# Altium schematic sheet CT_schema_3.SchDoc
size 578 x 363 mm
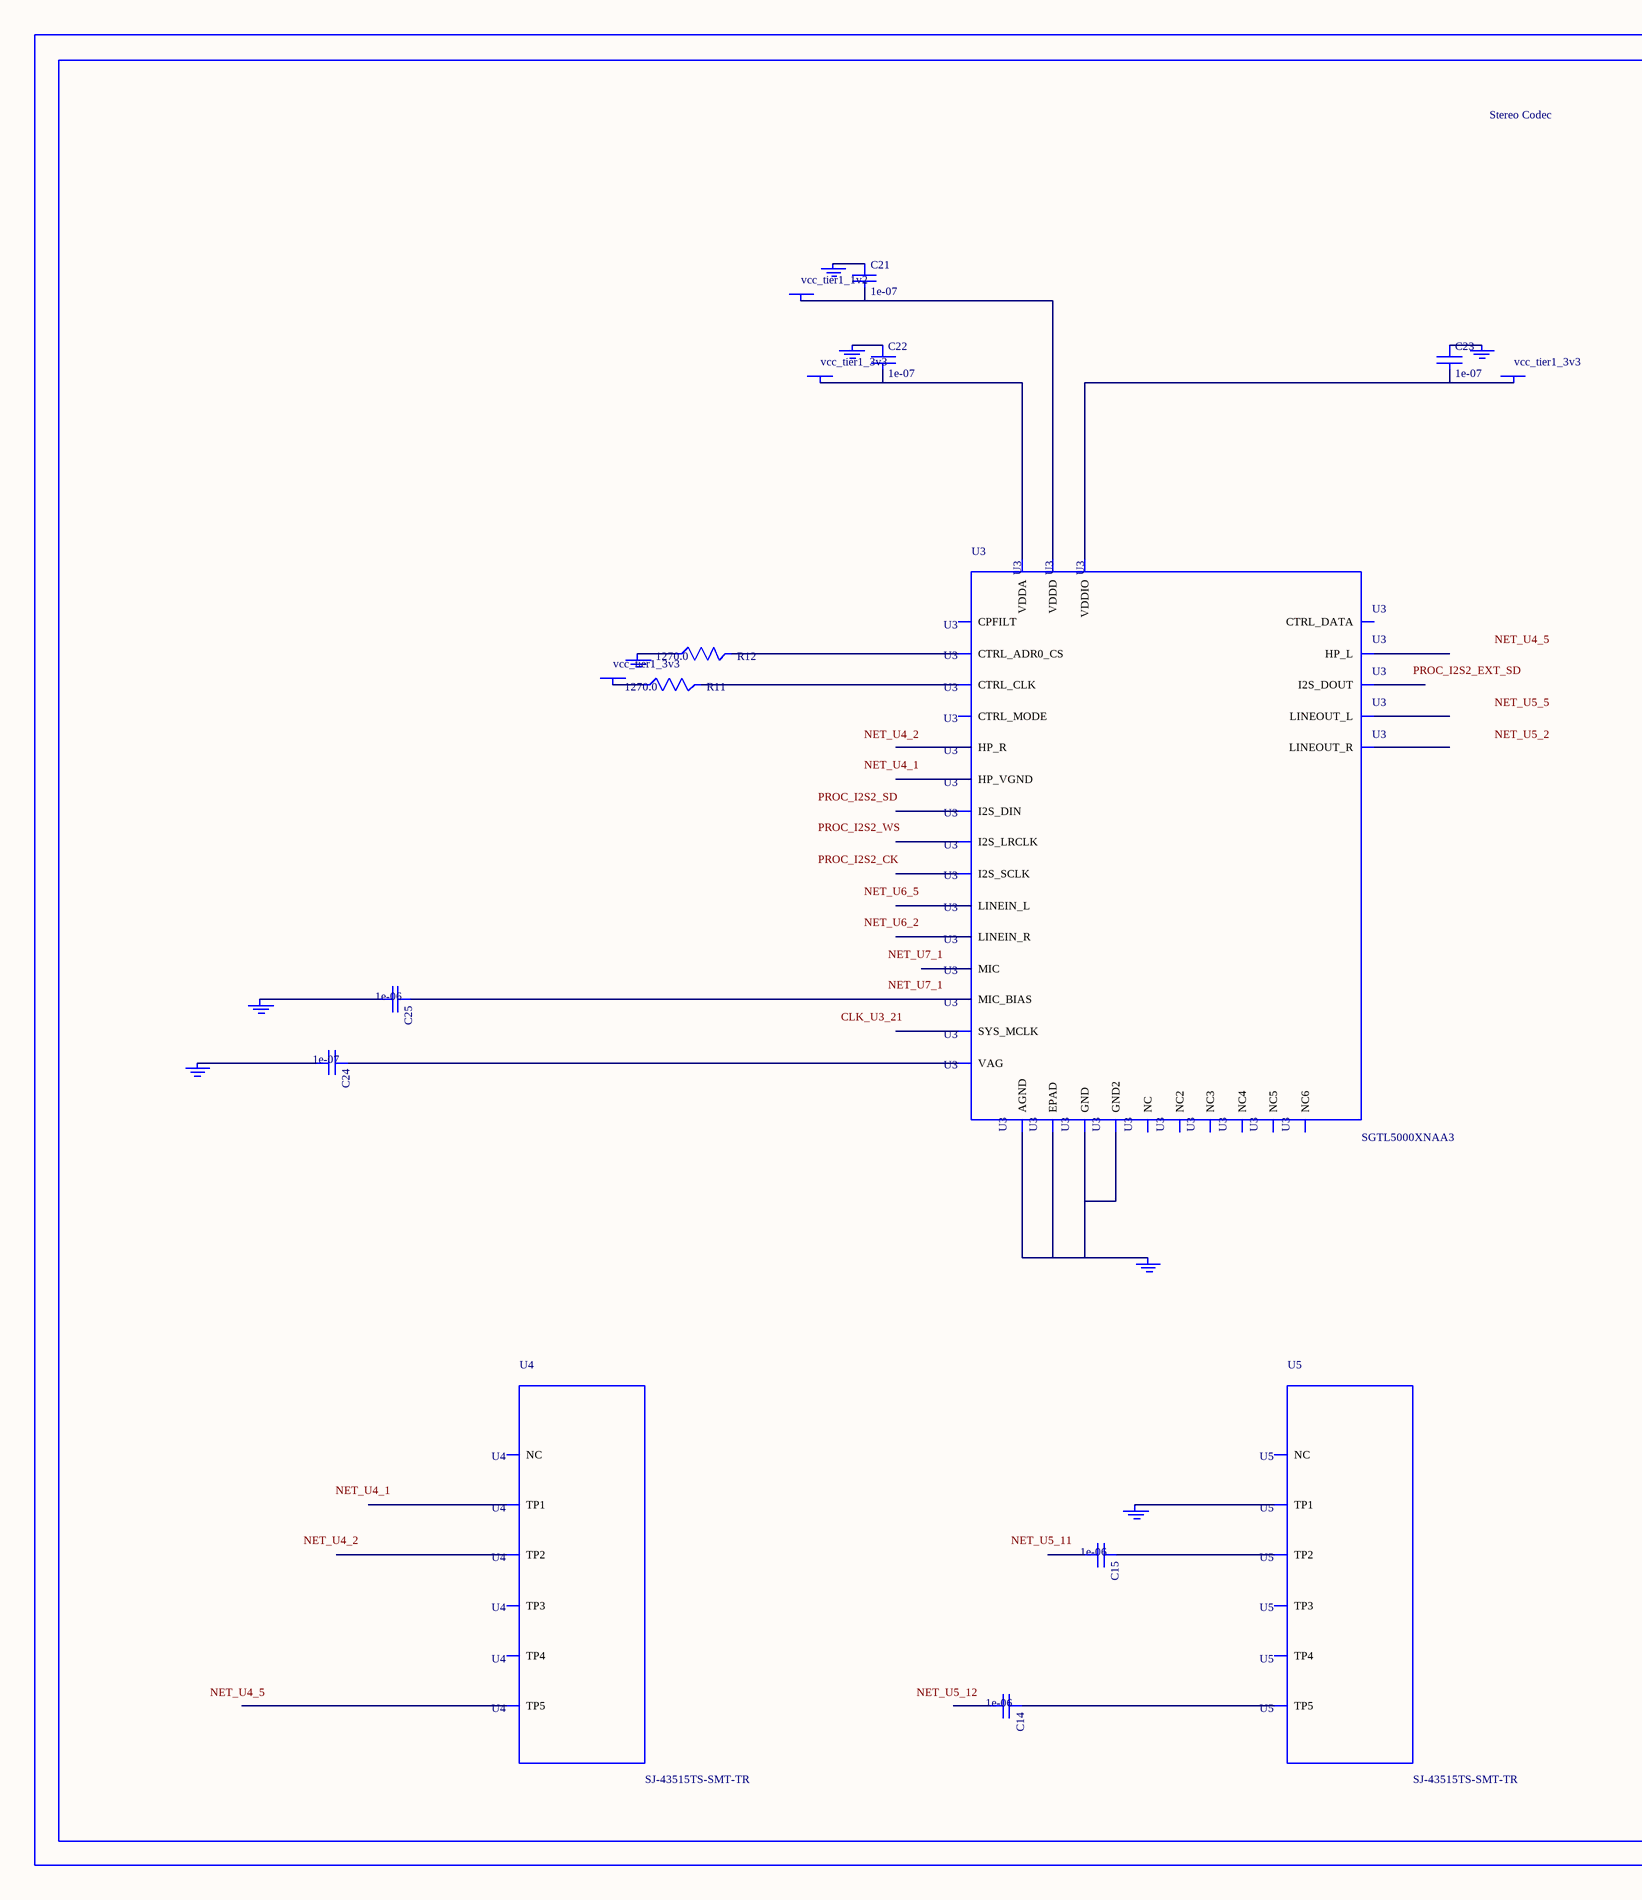
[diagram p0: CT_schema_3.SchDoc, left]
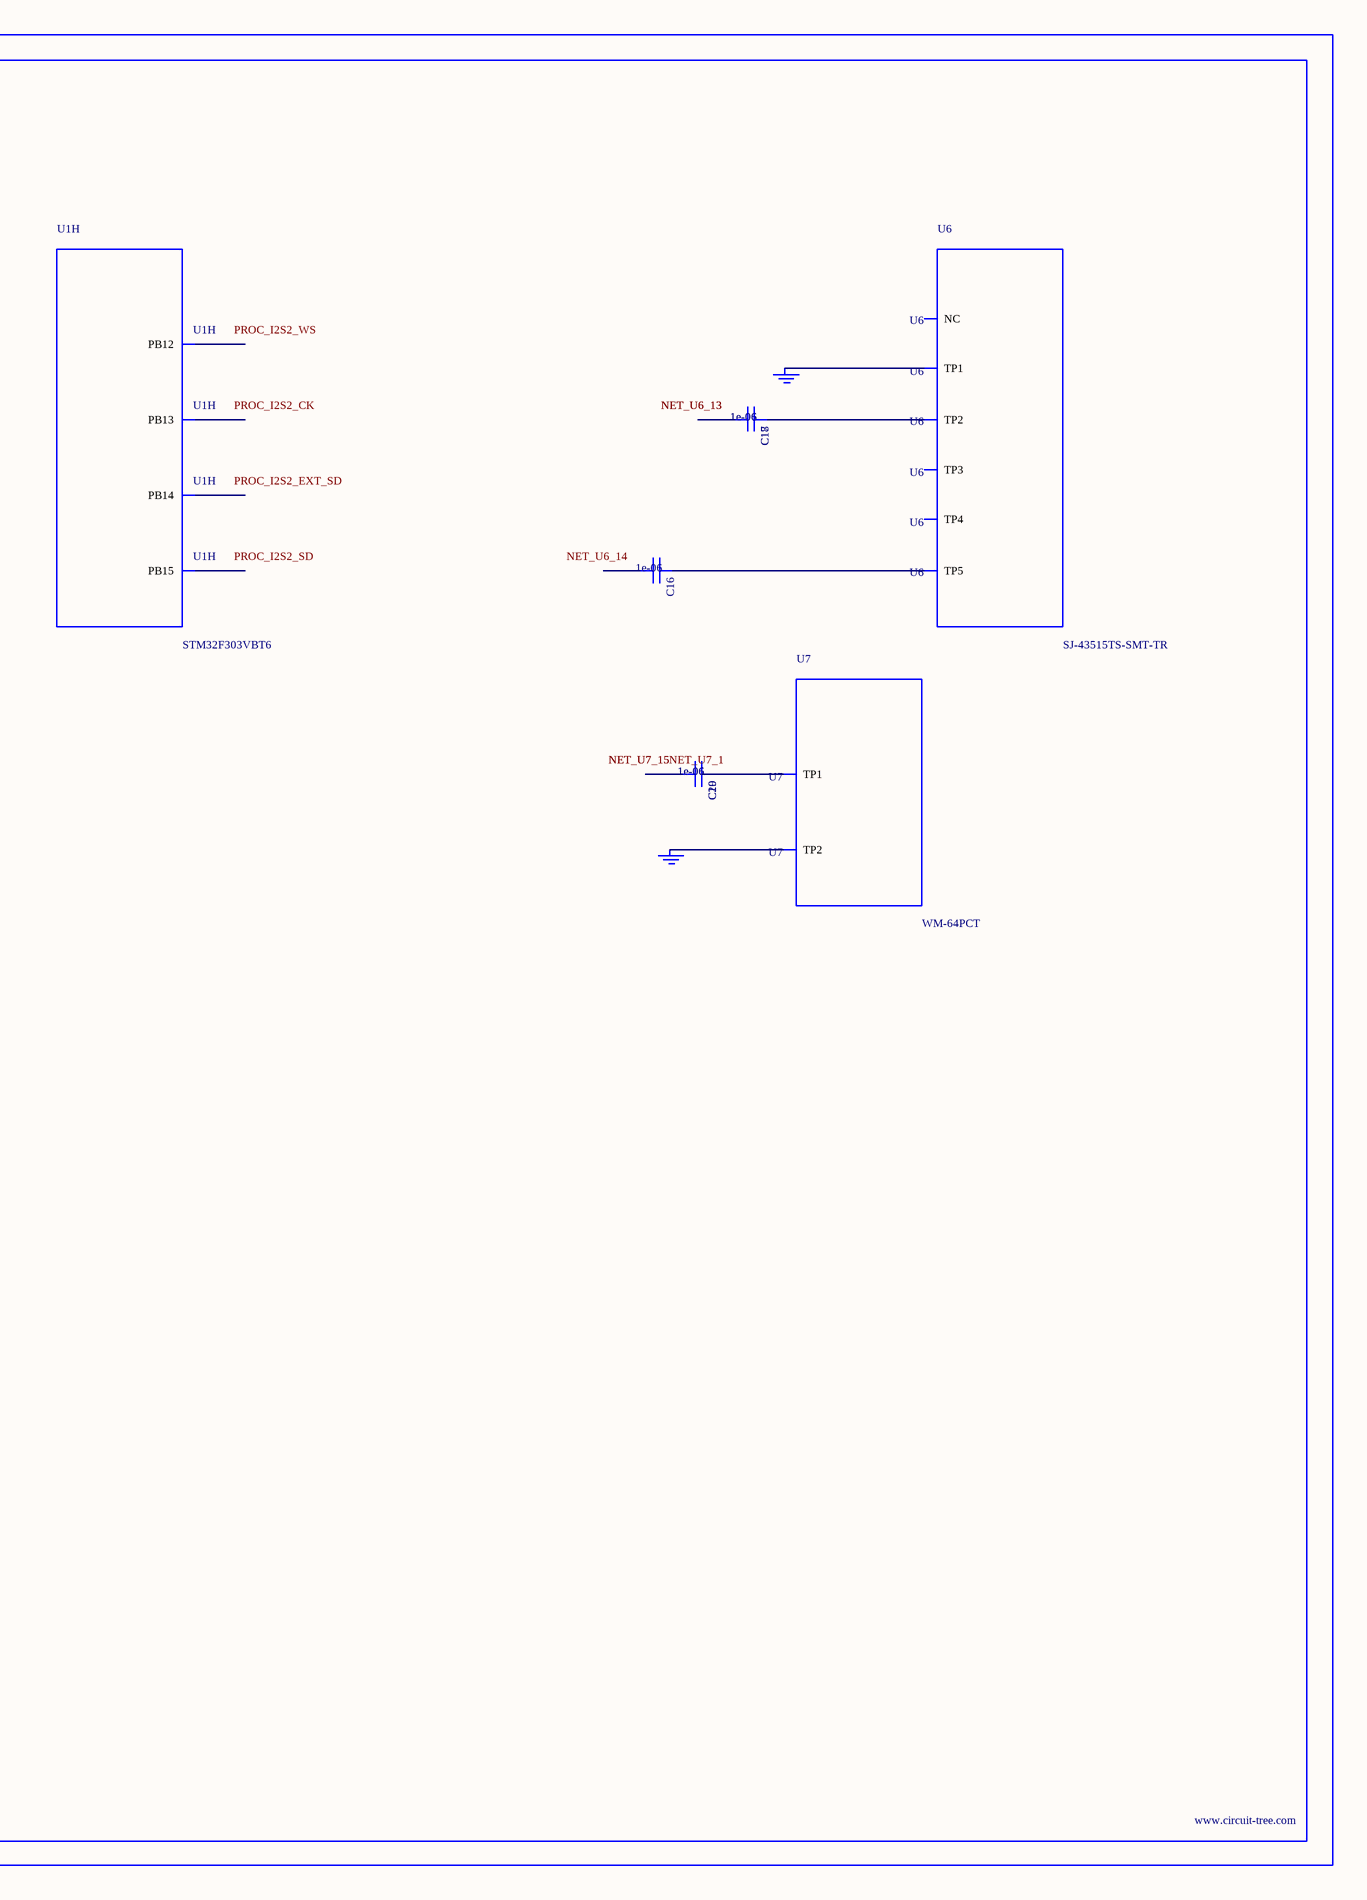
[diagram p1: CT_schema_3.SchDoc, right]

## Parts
BORDER2  (no value)
C14  1e-06  [C0603]
C15  1e-06  [C0603]
C16  1e-06  [C0603]
C17  1e-06  [C0603]
C18  1e-06  [C0603]
C19  1e-06  [C0603]
C20  1e-06  [C0603]
C21  1e-07  [C0402]
C22  1e-07  [C0402]
C23  1e-07  [C0402]
C24  1e-07  [C0402]
C25  1e-06  [C0603]
GND_INSTANCE_2_0  (no value)
GND_INSTANCE_2_1  (no value)
GND_INSTANCE_2_2  (no value)
GND_INSTANCE_2_3  (no value)
GND_INSTANCE_2_4  (no value)
GND_INSTANCE_2_5  (no value)
GND_INSTANCE_2_6  (no value)
GND_INSTANCE_2_7  (no value)
GND_INSTANCE_2_8  (no value)
GND_INSTANCE_2_9  (no value)
GND_INSTANCE_2_10  (no value)
POWER_INSTANCE_2_0  vcc_tier1_3v3
POWER_INSTANCE_2_1  vcc_tier1_3v3
POWER_INSTANCE_2_2  vcc_tier1_3v3
POWER_INSTANCE_2_3  vcc_tier1_1v2
R11  1270.0  [R0603]
R12  1270.0  [R0603]
U1  STM32F303VBT6  [LQFP100]  (part H of 9)
U3  SGTL5000XNAA3  [QFN-32]
U4  SJ-43515TS-SMT-TR  [SJ-43515TS-SMT-TR]
U5  SJ-43515TS-SMT-TR  [SJ-43515TS-SMT-TR]
U6  SJ-43515TS-SMT-TR  [SJ-43515TS-SMT-TR]
U7  WM-64PCT  [WM-64PC]

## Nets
NetC14_1: C14.1 U5.5(TP5)
NetC15_1: C15.1 U5.2(TP2)
NetC16_1: C16.1 U6.5(TP5)
NetC17_1: C17.1 C18.1 U6.2(TP2)
NetC17_2: C17.2 C18.2
NetC19_1: C19.1 C20.1 U7.1(TP1)
NetC19_2: C19.2 C20.2
NetC21_1: C21.1 GND_INSTANCE_2_5.0(GND)
NetC21_2: C21.2 POWER_INSTANCE_2_3.0(PWR) U3.30(VDDD)
NetC22_1: C22.1 GND_INSTANCE_2_1.0(GND)
NetC22_2: C22.2 POWER_INSTANCE_2_0.0(PWR) U3.5(VDDA)
NetC23_1: C23.1 GND_INSTANCE_2_4.0(GND)
NetC23_2: C23.2 POWER_INSTANCE_2_1.0(PWR) U3.20(VDDIO)
NetC24_1: C24.1 U3.10(VAG)
NetC24_2: C24.2 GND_INSTANCE_2_2.0(GND)
NetC25_1: C25.1 U3.16(MIC_BIAS)
NetC25_2: C25.2 GND_INSTANCE_2_3.0(GND)
NetGND_INSTANCE_2_0_0: GND_INSTANCE_2_0.0(GND) U3.1(GND) U3.3(GND2) U3.7(AGND) U3.EXP(EPAD)
NetGND_INSTANCE_2_6_0: GND_INSTANCE_2_6.0(GND) R12.1
NetGND_INSTANCE_2_7_0: GND_INSTANCE_2_7.0(GND) U5.1(TP1)
NetGND_INSTANCE_2_8_0: GND_INSTANCE_2_8.0(GND) GND_INSTANCE_2_9.0(GND) U6.1(TP1)
NetGND_INSTANCE_2_10_0: GND_INSTANCE_2_10.0(GND) U7.2(TP2)
NetPOWER_INSTANCE_2_2_0: POWER_INSTANCE_2_2.0(PWR) R11.1
NetR11_2: R11.2 U3.29(CTRL_CLK)
NetR12_2: R12.2 U3.31(CTRL_ADR0_CS)

Not connected (* = marked no-connect by the designer): C14 2; C15 2; C16 2; U1 51(PB12) 52(PB13) 53(PB14) 54(PB15); U3 2(HP_R) 4(HP_VGND) 6(HP_L) 8(NC) 9(NC2) 11(LINEOUT_R) 12(LINEOUT_L) 13(LINEIN_R) 14(LINEIN_L) 15(MIC) 17(NC3) 18(CPFILT) 19(NC4) 21(SYS_MCLK) 22(NC5) 23(I2S_LRCLK) 24(I2S_SCLK) 25(I2S_DOUT) 26(I2S_DIN) 27(CTRL_DATA) 28(NC6) 32(CTRL_MODE); U4 1(TP1) 2(TP2) 3(TP3) 4(TP4) 5(TP5) 6(NC); U5 3(TP3) 4(TP4) 6(NC); U6 3(TP3) 4(TP4) 6(NC)

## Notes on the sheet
- Labels drawn without touching a wire or pin: CLK_U3_21, NET_U4_1, NET_U4_2, NET_U4_5, NET_U5_2, NET_U5_5, NET_U5_11, NET_U5_12, NET_U6_2, NET_U6_5, NET_U6_14, NET_U7_1, PROC_I2S2_CK, PROC_I2S2_EXT_SD, PROC_I2S2_SD, PROC_I2S2_WS

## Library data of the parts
BORDER2 = BORDER_PAGE2
C14-C20 C25 = C0603C105K3RACTU
C21-C24 = C0402C104K3RACTU
GND_INSTANCE_2_0-GND_INSTANCE_2_10 = GND
POWER_INSTANCE_2_0-POWER_INSTANCE_2_3 = PWR
R11 R12 = RC0603FR-071K27L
